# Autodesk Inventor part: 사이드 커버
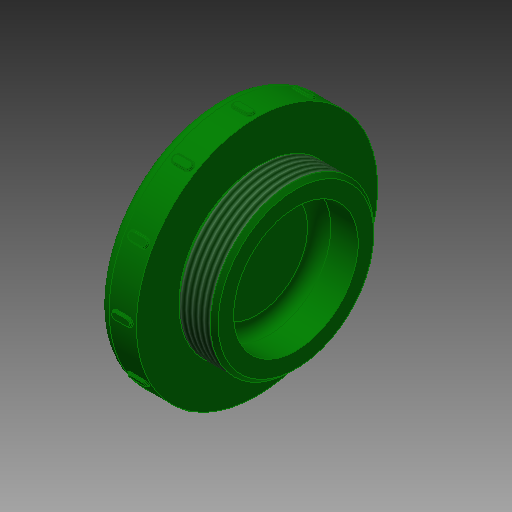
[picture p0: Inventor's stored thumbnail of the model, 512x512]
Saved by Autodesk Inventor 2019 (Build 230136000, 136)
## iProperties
Created: 2016-08
Part Number: 사이드 커버
Material: 스테인리스강
Document SubType Name: Modeling
Designer: mduedu
Density: 8.08 g/cm^3
Appearance: 진녹색
Author: mduedu
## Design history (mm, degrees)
sketch "스케치1"
  geometry: L1 (-5, 0)-(5, 0); L2 (-5, 0)-(-5, 31); L3 (-5, 31)-(5, 31); L4 (5, 31)-(5, 21); L5 (5, 21)-(15, 21); L6 (15, 21)-(15, 16); L7 (15, 16)-(5, 16); L8 (5, 16)-(5, 0); 2 further points
  constraints: 16 end point, 4 parallel, 2 perpendicular, 1 coincident, 1 collinear, 1 horizontal, 1 midpoint, 1 vertical
  dimensions: "d0" = 10 distance of L1.start L1.end; "d2" = 62 diameter of L3 L1; "d3" = 42 diameter of L5 L1; "d4" = 10 distance between parallel lines of L6 L8; "d5" = 5 distance of L5.end L6.end
revolve "회전1" sketch "스케치1" stored, may be unused: angle "d6" = 90 deg
fillet "모깎기1" dims "d7" = 3
sketch "스케치2"
  geometry: L1 (5, -31)-(5, 31) reference; L2 (5, 21)-(15, 21) reference; L3 (0, 0)-(5, 0); L4 (5, 21)-(6, 21); L5 (6, 21)-(6, 20); L6 (6, 20)-(5, 20); L7 (5, 20)-(5, 21)
  constraints: 10 end point, 2 parallel, 1 horizontal, 1 midpoint, 1 perpendicular
  dimensions: "d8" = 1 distance of L2.start L4.end; "d9" = 40 diameter of L6 L3
revolve "회전2" sketch "스케치2" stored, may be unused: angle "d10" = 90 deg
fillet "모깎기2" dims "d11" = 3
feature "스레드1" dims "d12" = 10, "d13" = 0
chamfer "모따기1" distance "d14" = 1; stored, may be unused: second distance "d15" = 2, angle "d16" = 45 deg
node "작업 평면1"
sketch "스케치3"
  geometry: L1 (1, -1)-(-4, -1); L2 (-4, -1)-(-4, 1); L3 (-4, 1)-(1, 1); L4 (1, 1)-(1, -1); 2 further points
  constraints: 8 end point, 2 parallel, 1 horizontal, 1 horizontal alignment, 1 midpoint, 1 perpendicular
  dimensions: "d18" = 2 distance of L3.end L1.start; "d20" = 5 distance of L1.start L1.end; "d21" = 1 distance from line of L4 point (0, 0)
extrude "돌출1" join sketch "스케치3" stored distance "d22" = 10; taper "d23" = 0 deg
fillet "모깎기3" dims "d24" = 1
fillet "모깎기4" dims "d25" = 0.2
sketch "스케치4"
  geometry: 2 further points
  constraints: 1 coincident, 1 other
feature "엠보싱1" sketch "스케치4" dims "d0" = 10, "d2" = 62, "d3" = 42, "d4" = 10, "d5" = 5, "d29" = 0.5, "d30" = 0
node "솔리드1"
pattern_circular "원형 패턴1" dims angle "d27" = 360 deg
other parameters: "d17" = 31.5
